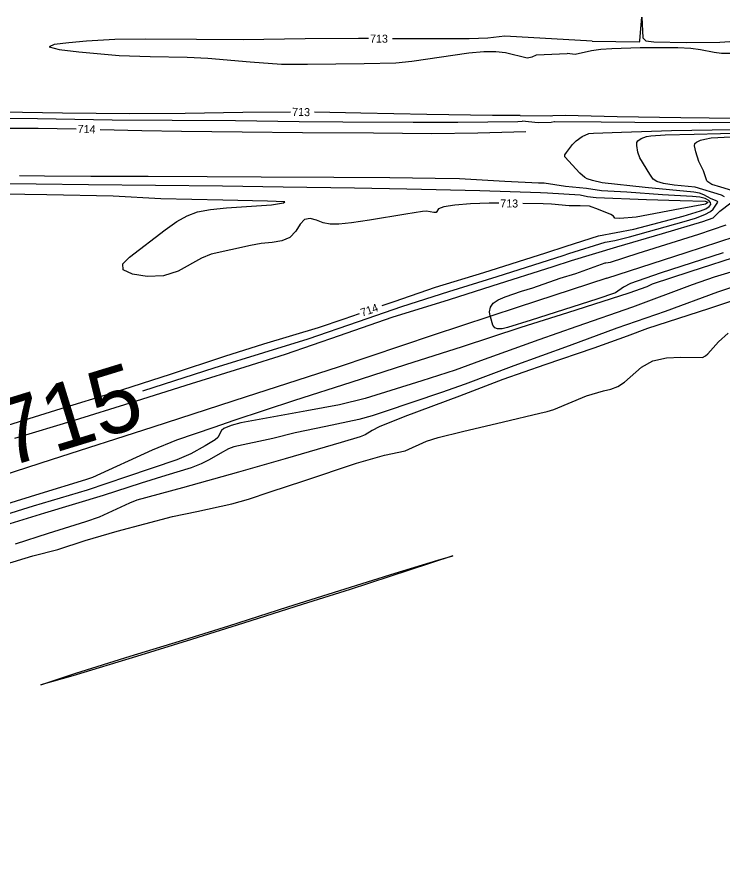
# Model space of a CAD drawing. Extents: x -468548933 to 3387700, y -306089263 to 1207014.
# Drawn here: x 1837456.7 to 1837809.5, y 535892.7 to 536318.5 of the extents above; entities that cross this region are included whole.
import ezdxf

# ---------------------------------------------------------------- set-up
doc = ezdxf.new("R2010")
doc.units = 0
for name, color, linetype in [('DT_X_Contour_Minor', 7, 'Continuous'), ('Level 14', 7, 'Continuous'), ('Level 19', 7, 'Continuous')]:
    doc.layers.add(name, color=color, linetype=linetype)

msp = doc.modelspace()

# ---------------------------------------------------------------- linework, layer by layer
at = {"layer": 'DT_X_Contour_Minor'}
for points in [[(1837744.11, 536306.4), (1837767.7, 536306.07), (1837767.94, 536306.69), (1837768.25, 536310.79), (1837768.89, 536318.51), (1837769.42, 536308.07), (1837770.92, 536306.67), (1837774.97, 536306.12), (1837791.03, 536305.81), (1837807.97, 536305.94), (1837817.87, 536306.7)], [(1837632.37, 536307.76), (1837627.39, 536307.81), (1837600.68, 536307.68), (1837569.73, 536307.17), (1837546.41, 536307.32), (1837520.98, 536307.53), (1837505.54, 536307.28), (1837491.49, 536306.41), (1837482.68, 536305.66), (1837475.28, 536304.71), (1837472.86, 536303.58), (1837477.8, 536302.32), (1837487.59, 536301.08), (1837507.7, 536299.36), (1837523.35, 536298.78), (1837541.75, 536298.46), (1837552.16, 536298), (1837573.23, 536296.17), (1837588.94, 536294.94), (1837601.89, 536294.91), (1837630.17, 536295.21), (1837645.94, 536295.63), (1837654.04, 536296.39), (1837682.46, 536300.54), (1837689.97, 536301.23), (1837695.97, 536301.27), (1837700.87, 536300.71), (1837711.59, 536298.2), (1837714.2, 536298.66), (1837716.3, 536299.69), (1837731.69, 536300.33)], [(1837744.11, 536306.4), (1837700.47, 536309.02), (1837691.96, 536308.02), (1837682.65, 536307.65), (1837650.56, 536307.58), (1837644.37, 536307.64)], [(1837813.33, 536300.26), (1837808.78, 536300.36), (1837805.15, 536300.73), (1837798.18, 536302.09), (1837793.37, 536302.71), (1837787, 536303.05), (1837768.11, 536303.13), (1837753.88, 536302.67), (1837748.51, 536302.27), (1837743.85, 536301.65), (1837735.68, 536299.72), (1837731.69, 536300.33)], [(1836847.77, 536270.24), (1836871.61, 536269.92), (1836892.04, 536269.57), (1836921.53, 536269.14), (1836952.66, 536268.92), (1836985.11, 536268.61), (1837011.29, 536268.33), (1837043.52, 536267.98), (1837073.09, 536267.57), (1837103.5, 536267.25), (1837135.62, 536266.87), (1837162.76, 536266.82), (1837194.37, 536266.53), (1837225.82, 536266.1), (1837257.42, 536265.59), (1837284.99, 536265.3), (1837309.39, 536264.97), (1837345.12, 536264.25), (1837381.18, 536263.42), (1837407.15, 536263.11), (1837437.74, 536262.96), (1837467.37, 536262.91), (1837486.25, 536262.61)], [(1837593.46, 536271.03), (1837569.51, 536270.84), (1837540.79, 536270.32), (1837513.1, 536270.15), (1837479.4, 536270.49), (1837449.54, 536271)], [(1837708.18, 536269.22), (1837694.28, 536269.23), (1837661.57, 536269.84), (1837628.59, 536270.41), (1837605.46, 536270.91)], [(1837708.18, 536269.22), (1837723.42, 536269.07), (1837723.65, 536269.2), (1837724.55, 536269.35), (1837730.64, 536269.44), (1837756.7, 536268.86), (1837788.4, 536268.26), (1837816.67, 536267.89), (1837848.14, 536267.79), (1837849.77, 536267.47), (1837850.35, 536267.08), (1837850.3, 536266.24), (1837849.81, 536266.15), (1837847.04, 536266.15), (1837821.72, 536265.84), (1837797.53, 536265.66), (1837765.37, 536265.85), (1837748.69, 536265.97), (1837725.26, 536266.18), (1837725.17, 536266.05), (1837723.64, 536265.84), (1837717.13, 536265.67), (1837709.15, 536266.45)], [(1837438.47, 536268), (1837467.05, 536267.76), (1837504.29, 536267.15), (1837534.28, 536266.98), (1837565.86, 536266.75), (1837597.65, 536266.3), (1837619.48, 536266.13), (1837654.71, 536265.96), (1837676.97, 536265.98), (1837707.04, 536266.29), (1837709.15, 536266.45)], [(1837498.25, 536262.31), (1837519.06, 536261.72), (1837538.97, 536261.43), (1837569.3, 536261.09), (1837599.41, 536260.86), (1837634.92, 536260.7), (1837663.78, 536260.38), (1837686.94, 536260.61), (1837710.96, 536261.33)], [(1837732.5, 536200.28), (1837750.7, 536206.03), (1837755.46, 536206.88), (1837762.8, 536208.68), (1837790.11, 536216.32), (1837795.76, 536218.06), (1837800.36, 536219.76), (1837803.2, 536221.25), (1837804.64, 536222.51), (1837806.88, 536225.93), (1837806.79, 536226.23), (1837805.76, 536226.73), (1837803.51, 536227.72), (1837799.96, 536229.69), (1837797.68, 536230.54), (1837794.93, 536231.04), (1837770.61, 536233.25), (1837749.18, 536235.61), (1837744.26, 536236.74), (1837741.61, 536237.6), (1837740.41, 536238.27), (1837738.02, 536240.5), (1837730.55, 536248.68), (1837730.55, 536249.63), (1837731.28, 536250.86), (1837734.37, 536254.77), (1837736.18, 536256.66), (1837739.19, 536258.83), (1837742.53, 536260.22), (1837744.71, 536260.44), (1837758.77, 536261), (1837783.76, 536261.81), (1837814.22, 536262.25)], [(1837810.31, 536228.7), (1837808.81, 536229.43), (1837795.56, 536233.41), (1837785.1, 536234.43), (1837779.8, 536235.25), (1837776.48, 536236.32), (1837774.64, 536237.53), (1837772.89, 536239.91), (1837767.89, 536248.22), (1837767.02, 536251.02), (1837766.38, 536254.32), (1837766.43, 536255.73), (1837766.9, 536256.71), (1837768.65, 536257.85), (1837771.21, 536258.77), (1837773.51, 536259.16), (1837780.67, 536259.69), (1837795.13, 536260.01), (1837821.4, 536260.63)], [(1837816.5, 536230.93), (1837808.45, 536233.5), (1837803.93, 536234.85), (1837801.91, 536236.07), (1837801.41, 536236.65), (1837799.68, 536241.6), (1837797.47, 536246.34), (1837795.87, 536251.08), (1837795.22, 536254.14), (1837795.38, 536255.36), (1837796.2, 536256), (1837798.31, 536256.94), (1837800.38, 536257.54), (1837803.63, 536258.08), (1837813.41, 536258.69)], [(1837373.2, 536236.28), (1837406.37, 536235.81), (1837435.05, 536235.48), (1837466.38, 536235.17), (1837492.39, 536234.87), (1837525.96, 536234.53), (1837559.46, 536234.18), (1837589.67, 536233.72), (1837625.38, 536233.08), (1837651.49, 536232.69), (1837688.01, 536231.8), (1837718.3, 536230.77), (1837721.77, 536230.7)], [(1837720.11, 536235.4), (1837717.39, 536235.41), (1837700.43, 536236.3), (1837677.8, 536237.62), (1837665.62, 536237.86), (1837643.09, 536238.07), (1837615.09, 536238.24), (1837578.8, 536238.48), (1837551.74, 536238.62), (1837522.31, 536238.76), (1837493.67, 536238.86), (1837470.4, 536239.05), (1837457.97, 536239.13)], [(1837731.17, 536204.06), (1837747.34, 536209.23), (1837765.02, 536212.51), (1837789.56, 536219.06), (1837798.24, 536221.6), (1837800.98, 536222.68), (1837802.64, 536223.73), (1837803.34, 536224.76), (1837803.21, 536225.8), (1837802.36, 536226.83), (1837800.66, 536227.75), (1837797.98, 536228.44), (1837794.24, 536228.82), (1837779.21, 536229.65), (1837761.44, 536230.97), (1837748.87, 536231.71), (1837741.28, 536232.86), (1837730.84, 536233.87), (1837720.11, 536235.4)], [(1837697.43, 536225.4), (1837692.58, 536225.45), (1837683.4, 536225.15), (1837675.54, 536224.56), (1837669.99, 536223.67), (1837667.35, 536222.57), (1837666.15, 536220.88), (1837665, 536220.82), (1837661.29, 536221.41), (1837659.32, 536221.39), (1837650.98, 536219.96), (1837632.85, 536216.91), (1837623.93, 536215.6), (1837617.53, 536214.95), (1837613.14, 536214.99), (1837609.69, 536215.73), (1837606.35, 536216.96), (1837603.17, 536217.84), (1837600.41, 536217.37), (1837598.19, 536214.94), (1837595.98, 536211.5), (1837593.12, 536208.4), (1837589.1, 536206.65), (1837584.18, 536205.86), (1837578.8, 536205.28), (1837573.36, 536204.34), (1837553.7, 536200.01), (1837548.85, 536198.02), (1837537.27, 536191.55), (1837530, 536189.19), (1837521.8, 536188.75), (1837514.37, 536189.95), (1837509.79, 536192.21), (1837509.57, 536195.08), (1837512.87, 536198.52), (1837530.71, 536212.11), (1837536.58, 536216.25), (1837541.75, 536219.23), (1837547, 536221.18), (1837553.34, 536222.39), (1837561.4, 536223.15), (1837583.82, 536224.67), (1837589.97, 536225.71), (1837590.59, 536226.13), (1837581.86, 536226.4), (1837559.52, 536226.95), (1837528.62, 536227.7), (1837504.74, 536228.93), (1837471.62, 536229.59), (1837438.29, 536230.13)], [(1837721.77, 536230.7), (1837738.17, 536229.68), (1837741.72, 536228.77), (1837746.13, 536228.36), (1837771.33, 536227.25), (1837788.14, 536226.73), (1837800.52, 536226.46), (1837801.94, 536226.03), (1837801.82, 536225.57), (1837800.68, 536225.05), (1837788.16, 536222.59), (1837766.18, 536218.52), (1837757.92, 536217.84), (1837755.39, 536217.99), (1837755.1, 536218.52), (1837754.74, 536219), (1837753.38, 536219.81), (1837747.36, 536222.34), (1837742.71, 536223.98), (1837738.14, 536224.07), (1837732.66, 536224.21), (1837723.76, 536225.06)], [(1837723.76, 536225.06), (1837719.6, 536225.15), (1837709.42, 536225.26)], [(1837733.75, 536196.75), (1837756.37, 536203.61), (1837779.32, 536210.35), (1837799.44, 536216.25), (1837804.53, 536218.19), (1837807.85, 536221.49), (1837813.38, 536225.64)], [(1837736, 536190.36), (1837750.64, 536195.67), (1837750.97, 536195.59), (1837753.32, 536196.07), (1837767.15, 536200.41), (1837797.47, 536210.04), (1837811.13, 536214.69)], [(1837639.11, 536174.28), (1837645.15, 536176.4), (1837665.88, 536183.41), (1837690.01, 536190.84), (1837720.92, 536200.57), (1837731.17, 536204.06)], [(1837519.55, 536131.6), (1837525.33, 536133.43), (1837555.32, 536143.15), (1837580.1, 536150.82), (1837602.25, 536157.74), (1837627.31, 536166.41), (1837648.97, 536173.9), (1837672.52, 536181.4), (1837696.61, 536188.87), (1837729.68, 536199.37), (1837732.49, 536200.31)], [(1837819.78, 536199.9), (1837792.98, 536191.22), (1837774.16, 536184.98), (1837771.44, 536183.74), (1837762.37, 536180.51), (1837731.77, 536170.63), (1837708.54, 536163.25), (1837679.14, 536153.64), (1837650.8, 536144.73), (1837623.59, 536135.92), (1837595.46, 536126.84), (1837565.01, 536116.83), (1837555.05, 536113.29), (1837536.49, 536106.98), (1837524.19, 536101.99)], [(1837809.6, 536200.63), (1837778.12, 536190.46), (1837763.31, 536185.26), (1837759.71, 536183.51), (1837755.74, 536180.6), (1837746.38, 536177.45), (1837713.69, 536167.03), (1837701.77, 536163.31), (1837699.11, 536162.73), (1837696.86, 536162.62), (1837695.42, 536163.22), (1837694.56, 536164.5), (1837693.26, 536168.69), (1837693.07, 536170.05)], [(1837824.65, 536194.27), (1837805.15, 536188.46), (1837794.01, 536184.6), (1837764.36, 536173.47), (1837736.43, 536163.82), (1837717.41, 536157.14), (1837688.31, 536146.61), (1837675.7, 536141.96), (1837658.95, 536136.66), (1837630.65, 536127.8), (1837617.81, 536124.71), (1837601.48, 536121.64), (1837568.65, 536115.61), (1837563.81, 536114.35), (1837560.09, 536112.81), (1837558.97, 536111.88), (1837557.06, 536108.37), (1837555.69, 536107.11), (1837550.82, 536104.1), (1837543.53, 536100.22), (1837536.55, 536097.17), (1837511.51, 536088.64), (1837491.72, 536082.07), (1837464.88, 536073.99), (1837448.33, 536068.85)], [(1837455.63, 536107.97), (1837485.47, 536116.98), (1837513.27, 536125.66), (1837543.91, 536135.39), (1837570.67, 536143.65), (1837590.88, 536149.93), (1837617.88, 536159.37), (1837644.25, 536168.42), (1837672.76, 536177.4), (1837694.13, 536184.12), (1837724.56, 536193.76), (1837733.75, 536196.75)], [(1837693.07, 536170.05), (1837692.9, 536171.18), (1837693.27, 536173.52), (1837694.7, 536175.48), (1837697.18, 536177.14), (1837700.58, 536178.65), (1837708.74, 536181.45), (1837714.47, 536183.21), (1837728.06, 536187.93), (1837736, 536190.36)], [(1837820.29, 536185.44), (1837806.69, 536181.06), (1837780.54, 536171.38), (1837756.48, 536162.94), (1837732.59, 536154.23), (1837704.94, 536144.18), (1837680.68, 536135.08), (1837668.91, 536130.81), (1837640.25, 536121.1), (1837634.18, 536119.15), (1837627.48, 536117.34), (1837610.99, 536113.9), (1837595.78, 536110.6), (1837584.6, 536107.84), (1837565.06, 536103.71), (1837562.4, 536102.72), (1837558.18, 536100.38), (1837552.76, 536097.17), (1837548.8, 536095.25), (1837543.8, 536093.25), (1837531.16, 536089.3), (1837518.79, 536085.53), (1837499.81, 536079.37), (1837470.44, 536070.49), (1837444.25, 536062.56)], [(1837827.33, 536180.96), (1837802.25, 536172.69), (1837771.71, 536162.78), (1837761.66, 536159.08), (1837744.94, 536153), (1837720.49, 536144.59), (1837699.47, 536137.26), (1837677.88, 536128.98), (1837650.56, 536118.82), (1837637.63, 536113.66), (1837634.17, 536111.89), (1837630.74, 536109.69), (1837628.23, 536108.68), (1837618.75, 536105.83), (1837590.66, 536097.63), (1837567.47, 536090.98), (1837539.45, 536083.18), (1837516.64, 536077.03), (1837512.96, 536075.56), (1837497.71, 536068.6), (1837490.92, 536066.12), (1837472.34, 536060.3), (1837455.77, 536055.11)], [(1837446.69, 536112.86), (1837478.86, 536122.81), (1837504.88, 536130.91), (1837533.41, 536140.01), (1837560.5, 536148.97), (1837580.04, 536155.09), (1837607.44, 536163.41), (1837620.28, 536167.65), (1837627.79, 536170.29)], [(1837450.9, 536044.97), (1837464.6, 536049.16), (1837477.05, 536052.34), (1837490.86, 536056.94), (1837506.77, 536061.53), (1837534.36, 536068.78), (1837546.63, 536071.31), (1837564.03, 536075.23), (1837572.33, 536077.45), (1837583.19, 536081.15), (1837600.01, 536086.69), (1837626.32, 536095.51), (1837640.32, 536099.45), (1837650.69, 536101.76), (1837661.35, 536106.45), (1837667.18, 536108.29), (1837679.41, 536111.38), (1837699.89, 536116.15), (1837718, 536120.49), (1837721.67, 536121.31), (1837724.99, 536122.33), (1837741.29, 536129.19), (1837749.87, 536131.63), (1837753.52, 536132.53), (1837756.89, 536133.78), (1837760.32, 536135.99), (1837768.72, 536143.45), (1837774.43, 536146.63), (1837781.34, 536148.2), (1837788.36, 536148.56), (1837799.23, 536148.4), (1837800.8, 536149.12), (1837801.99, 536150.23), (1837807.31, 536156.18), (1837812.02, 536160.51)], [(1837524.19, 536101.99), (1837494.39, 536088.42), (1837490.96, 536087.13), (1837468.09, 536080.22), (1837451.45, 536075.06)], [(1837666.97, 536047.08), (1837674.45, 536049.17), (1837652.66, 536041.99), (1837623.12, 536032.45), (1837599.27, 536024.91), (1837569.95, 536015.53), (1837543.91, 536007.43), (1837516.45, 535998.96), (1837484.65, 535989.21), (1837468.61, 535984.67), (1837469.64, 535985.13), (1837486.05, 535990.52), (1837513.25, 535998.98), (1837537.96, 536006.61), (1837562.63, 536014.27), (1837592.01, 536023.69), (1837618.04, 536031.92), (1837645.61, 536040.5), (1837666.97, 536047.08)]]:
    msp.add_lwpolyline(points, dxfattribs=at)
at = {"layer": 'Level 14'}
for points in [[(1837751.38, 536188.04), (1837791.13, 536200.82), (1837831.94, 536214.15), (1837866.96, 536225.47), (1837979.86, 536263.14), (1838023.59, 536277.14), (1838067.23, 536291.44), (1838108.15, 536304.5)], [(1837751.39, 536188.05), (1837707.09, 536173.57), (1837664.71, 536159.54), (1837617.28, 536143.58), (1837571.21, 536128.71), (1837524.56, 536113.58), (1837473.85, 536097.14), (1837419.68, 536079.64), (1837372.42, 536064.34), (1837329.51, 536050.55), (1837285.99, 536036.61), (1837240.32, 536021.48), (1837193.97, 536006.62), (1837152.49, 535993.2), (1837108.37, 535978.6), (1837063.52, 535964.32), (1837019.79, 535950.03), (1836978.84, 535936.61), (1836933.82, 535922.16), (1836891.43, 535908.38), (1836843.39, 535892.69)]]:
    msp.add_lwpolyline(points, dxfattribs=at)

# ---------------------------------------------------------------- texts
at = {"layer": 'Level 19'}
for s, height, rotation, p in [('713', 4, 359.4393, (1837633.12, 536305.75)), ('713', 4, 358.7575, (1837594.19, 536269.15)), ('714', 4, 358.3622, (1837486.98, 536260.63)), ('713', 4, 359.3534, (1837698.17, 536223.39)), ('714', 4, 19.4118, (1837629.2, 536168.67)), ('715', 33, 17.0741, (1837451.6, 536093.3))]:
    msp.add_text(s, height=height, rotation=rotation, dxfattribs=at).set_placement(p)

doc.saveas('drawing.dxf')
